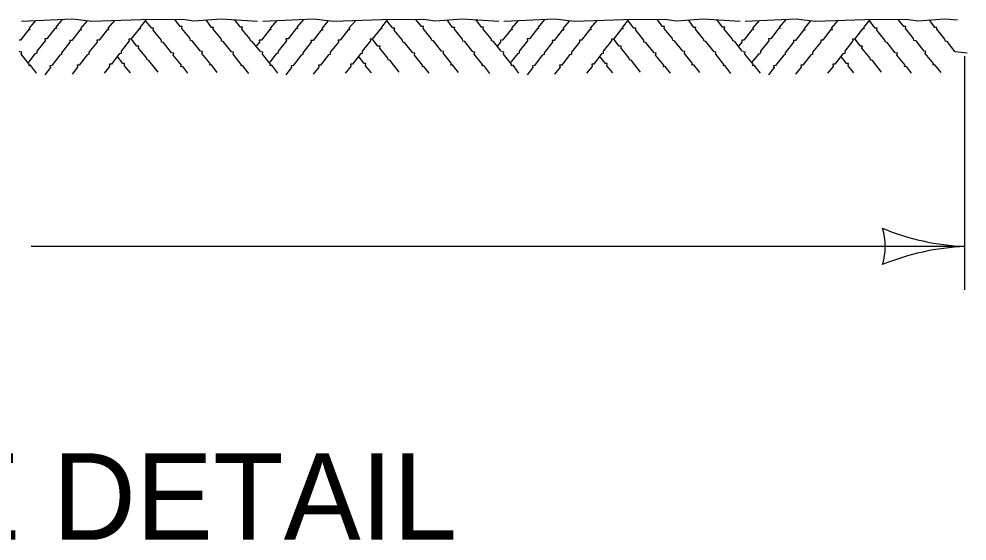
# Model space of a CAD drawing. Extents: x 49991.4 to 50021, y 49987.6 to 50011.4.
# Drawn here: x 50005.452 to 50006.329, y 49996.72 to 49997.202 of the extents above; entities that cross this region are included whole.
import ezdxf

# ---------------------------------------------------------------- set-up
doc = ezdxf.new("R2010")
doc.units = 0
for name, color, linetype in [('Level 1', 7, 'Continuous'), ('Level 2', 7, 'Continuous'), ('Level 3', 7, 'Continuous')]:
    doc.layers.add(name, color=color, linetype=linetype)

msp = doc.modelspace()

# ---------------------------------------------------------------- linework, layer by layer
at = {"layer": 'Level 1'}
for points in [[(50005.4675, 49997.2012), (50005.4615, 49997.1941), (50005.4623, 49997.1926), (50005.4609, 49997.1926), (50005.4535, 49997.183), (50005.4523, 49997.183)], [(50005.4545, 49997.2006), (50005.5017, 49997.2025), (50005.5195, 49997.2004), (50005.5649, 49997.2019), (50005.6037, 49997.2022), (50005.6141, 49997.2007), (50005.6393, 49997.2025), (50005.6584, 49997.2013), (50005.6729, 49997.2006)], [(50005.4921, 49997.202), (50005.4863, 49997.195), (50005.4869, 49997.1936), (50005.4855, 49997.1936), (50005.4779, 49997.184), (50005.4761, 49997.184), (50005.4763, 49997.1824), (50005.4687, 49997.1726), (50005.4687, 49997.171), (50005.467, 49997.1704), (50005.461, 49997.1626)], [(50005.5149, 49997.2004), (50005.5091, 49997.1936), (50005.5099, 49997.1923), (50005.5085, 49997.1923), (50005.5011, 49997.1827), (50005.4993, 49997.1827), (50005.4994, 49997.181), (50005.4917, 49997.1713), (50005.4917, 49997.1696), (50005.4899, 49997.1689), (50005.4827, 49997.1596), (50005.4809, 49997.1593), (50005.4814, 49997.1576), (50005.476, 49997.151)], [(50005.5405, 49997.2012), (50005.5345, 49997.1941), (50005.5353, 49997.1926), (50005.5337, 49997.1926), (50005.5264, 49997.183), (50005.5243, 49997.183), (50005.5247, 49997.1812), (50005.5169, 49997.1718), (50005.5169, 49997.1698), (50005.5153, 49997.1692), (50005.5079, 49997.1598), (50005.5061, 49997.1598), (50005.5065, 49997.1578), (50005.5013, 49997.1515)], [(50005.5699, 49997.202), (50005.5641, 49997.1947), (50005.5648, 49997.1935), (50005.5633, 49997.1935), (50005.5558, 49997.1839), (50005.554, 49997.1839), (50005.5541, 49997.1822), (50005.5467, 49997.1726), (50005.5467, 49997.1707), (50005.545, 49997.1702), (50005.5377, 49997.1608), (50005.5359, 49997.1606), (50005.5361, 49997.1587), (50005.5309, 49997.1524)], [(50005.6085, 49997.1524), (50005.6037, 49997.1587), (50005.6021, 49997.1584), (50005.6025, 49997.1598), (50005.5948, 49997.169), (50005.5954, 49997.171), (50005.5935, 49997.1712), (50005.5859, 49997.1808), (50005.5841, 49997.1812), (50005.584, 49997.183), (50005.5765, 49997.1922), (50005.5767, 49997.1941), (50005.575, 49997.1941), (50005.5697, 49997.2006)], [(50005.6357, 49997.153), (50005.6303, 49997.1602), (50005.6289, 49997.1599), (50005.629, 49997.1612), (50005.6215, 49997.1706), (50005.6219, 49997.1725), (50005.6201, 49997.1726), (50005.6125, 49997.1824), (50005.6109, 49997.1827), (50005.6105, 49997.1845), (50005.6029, 49997.1936), (50005.6033, 49997.1956), (50005.6014, 49997.1956), (50005.5963, 49997.202)], [(50005.6649, 49997.1522), (50005.6591, 49997.1596), (50005.6577, 49997.1592), (50005.6578, 49997.1605), (50005.6503, 49997.1701), (50005.6507, 49997.1718), (50005.6489, 49997.172), (50005.6413, 49997.1816), (50005.6397, 49997.1821), (50005.6395, 49997.1838), (50005.6319, 49997.193), (50005.6321, 49997.1947), (50005.6303, 49997.1947), (50005.6253, 49997.2016)], [(50005.6753, 49997.1726), (50005.6681, 49997.1816), (50005.6663, 49997.1822), (50005.6661, 49997.1839), (50005.6585, 49997.193), (50005.6589, 49997.195), (50005.6571, 49997.195), (50005.6517, 49997.2019)], [(50005.6908, 49997.2012), (50005.6848, 49997.1941), (50005.6854, 49997.1926), (50005.6841, 49997.1926), (50005.6765, 49997.183), (50005.6757, 49997.183)], [(50005.6779, 49997.2006), (50005.725, 49997.2025), (50005.7429, 49997.2004), (50005.7883, 49997.2019), (50005.8269, 49997.2022), (50005.8375, 49997.2007), (50005.8624, 49997.2025), (50005.8817, 49997.2013), (50005.8963, 49997.2006)], [(50005.7154, 49997.202), (50005.7094, 49997.195), (50005.7101, 49997.1936), (50005.7087, 49997.1936), (50005.7013, 49997.184), (50005.6993, 49997.184), (50005.6997, 49997.1824), (50005.692, 49997.1726), (50005.692, 49997.171), (50005.6903, 49997.1704), (50005.6843, 49997.1626)], [(50005.7381, 49997.2004), (50005.7325, 49997.1936), (50005.7333, 49997.1923), (50005.7317, 49997.1923), (50005.7243, 49997.1827), (50005.7223, 49997.1827), (50005.7227, 49997.181), (50005.7149, 49997.1713), (50005.7149, 49997.1696), (50005.7133, 49997.1689), (50005.7059, 49997.1596), (50005.7041, 49997.1593), (50005.7045, 49997.1576), (50005.6993, 49997.151)], [(50005.7639, 49997.2012), (50005.7575, 49997.1941), (50005.7583, 49997.1926), (50005.7569, 49997.1926), (50005.7495, 49997.183), (50005.7477, 49997.183), (50005.7478, 49997.1812), (50005.7401, 49997.1718), (50005.7401, 49997.1698), (50005.7385, 49997.1692), (50005.7311, 49997.1598), (50005.7295, 49997.1598), (50005.7298, 49997.1578), (50005.7244, 49997.1515)], [(50005.7933, 49997.202), (50005.7873, 49997.1947), (50005.788, 49997.1935), (50005.7867, 49997.1935), (50005.7791, 49997.1839), (50005.7773, 49997.1839), (50005.7775, 49997.1822), (50005.7699, 49997.1726), (50005.7699, 49997.1707), (50005.7681, 49997.1702), (50005.7609, 49997.1608), (50005.7591, 49997.1606), (50005.7593, 49997.1587), (50005.7539, 49997.1524)], [(50005.8317, 49997.1524), (50005.827, 49997.1587), (50005.8255, 49997.1584), (50005.8257, 49997.1598), (50005.8181, 49997.169), (50005.8185, 49997.171), (50005.8167, 49997.1712), (50005.8091, 49997.1808), (50005.8075, 49997.1812), (50005.8071, 49997.183), (50005.7995, 49997.1922), (50005.8, 49997.1941), (50005.7981, 49997.1941), (50005.7929, 49997.2006)], [(50005.8589, 49997.153), (50005.8534, 49997.1602), (50005.8519, 49997.1599), (50005.8523, 49997.1612), (50005.8449, 49997.1706), (50005.8451, 49997.1725), (50005.8433, 49997.1726), (50005.8359, 49997.1824), (50005.8341, 49997.1827), (50005.8337, 49997.1845), (50005.8263, 49997.1936), (50005.8264, 49997.1956), (50005.8247, 49997.1956), (50005.8195, 49997.202)], [(50005.8879, 49997.1522), (50005.8823, 49997.1596), (50005.8809, 49997.1592), (50005.8811, 49997.1605), (50005.8735, 49997.1701), (50005.8739, 49997.1718), (50005.8721, 49997.172), (50005.8647, 49997.1816), (50005.8629, 49997.1821), (50005.8625, 49997.1838), (50005.8551, 49997.193), (50005.8555, 49997.1947), (50005.8535, 49997.1947), (50005.8483, 49997.2016)], [(50005.8984, 49997.1726), (50005.8913, 49997.1816), (50005.8895, 49997.1822), (50005.8894, 49997.1839), (50005.8817, 49997.193), (50005.8821, 49997.195), (50005.8803, 49997.195), (50005.875, 49997.2019)], [(50005.914, 49997.2012), (50005.908, 49997.1941), (50005.9087, 49997.1926), (50005.9073, 49997.1926), (50005.8997, 49997.183), (50005.8989, 49997.183)], [(50005.9009, 49997.2006), (50005.9481, 49997.2025), (50005.9659, 49997.2004), (50006.0115, 49997.2019), (50006.0499, 49997.2022), (50006.0605, 49997.2007), (50006.0855, 49997.2025), (50006.1048, 49997.2013), (50006.1195, 49997.2006)], [(50005.9385, 49997.202), (50005.9327, 49997.195), (50005.9333, 49997.1936), (50005.932, 49997.1936), (50005.9245, 49997.184), (50005.9225, 49997.184), (50005.9229, 49997.1824), (50005.9151, 49997.1726), (50005.9151, 49997.171), (50005.9134, 49997.1704), (50005.9074, 49997.1626)], [(50005.9613, 49997.2004), (50005.9555, 49997.1936), (50005.9563, 49997.1923), (50005.9548, 49997.1923), (50005.9475, 49997.1827), (50005.9457, 49997.1827), (50005.9458, 49997.181), (50005.9381, 49997.1713), (50005.9381, 49997.1696), (50005.9365, 49997.1689), (50005.9291, 49997.1596), (50005.9273, 49997.1593), (50005.9277, 49997.1576), (50005.9224, 49997.151)], [(50005.9869, 49997.2012), (50005.9809, 49997.1941), (50005.9817, 49997.1926), (50005.9801, 49997.1926), (50005.9727, 49997.183), (50005.9709, 49997.183), (50005.971, 49997.1812), (50005.9635, 49997.1718), (50005.9635, 49997.1698), (50005.9615, 49997.1692), (50005.9545, 49997.1598), (50005.9525, 49997.1598), (50005.953, 49997.1578), (50005.9477, 49997.1515)], [(50006.0163, 49997.202), (50006.0105, 49997.1947), (50006.0113, 49997.1935), (50006.0099, 49997.1935), (50006.0023, 49997.1839), (50006.0004, 49997.1839), (50006.0005, 49997.1822), (50005.9929, 49997.1726), (50005.9929, 49997.1707), (50005.9914, 49997.1702), (50005.9841, 49997.1608), (50005.9823, 49997.1606), (50005.9825, 49997.1587), (50005.9773, 49997.1524)], [(50006.055, 49997.1524), (50006.0501, 49997.1587), (50006.0485, 49997.1584), (50006.0489, 49997.1598), (50006.0413, 49997.169), (50006.0418, 49997.171), (50006.04, 49997.1712), (50006.0323, 49997.1808), (50006.0305, 49997.1812), (50006.0304, 49997.183), (50006.0229, 49997.1922), (50006.0231, 49997.1941), (50006.0213, 49997.1941), (50006.0161, 49997.2006)], [(50006.0821, 49997.153), (50006.0767, 49997.1602), (50006.0749, 49997.1599), (50006.0754, 49997.1612), (50006.0679, 49997.1706), (50006.0683, 49997.1725), (50006.0664, 49997.1726), (50006.0589, 49997.1824), (50006.0573, 49997.1827), (50006.0569, 49997.1845), (50006.0493, 49997.1936), (50006.0497, 49997.1956), (50006.0478, 49997.1956), (50006.0429, 49997.202)], [(50006.1109, 49997.1522), (50006.1055, 49997.1596), (50006.1041, 49997.1592), (50006.1043, 49997.1605), (50006.0969, 49997.1701), (50006.0971, 49997.1718), (50006.0955, 49997.172), (50006.0879, 49997.1816), (50006.0861, 49997.1821), (50006.0857, 49997.1838), (50006.0783, 49997.193), (50006.0785, 49997.1947), (50006.0767, 49997.1947), (50006.0717, 49997.2016)], [(50006.1215, 49997.1726), (50006.1145, 49997.1816), (50006.1127, 49997.1822), (50006.1125, 49997.1839), (50006.1049, 49997.193), (50006.1053, 49997.195), (50006.1033, 49997.195), (50006.0981, 49997.2019)], [(50006.1371, 49997.2012), (50006.1311, 49997.1941), (50006.1318, 49997.1926), (50006.1303, 49997.1926), (50006.1229, 49997.183), (50006.1221, 49997.183)], [(50006.1241, 49997.2006), (50006.1714, 49997.2025), (50006.1889, 49997.2004), (50006.2349, 49997.2019), (50006.2733, 49997.2022), (50006.2839, 49997.2007), (50006.3088, 49997.2025), (50006.3207, 49997.2018)], [(50006.1618, 49997.202), (50006.1558, 49997.195), (50006.1565, 49997.1936), (50006.1551, 49997.1936), (50006.1479, 49997.184), (50006.1457, 49997.184), (50006.1461, 49997.1824), (50006.1384, 49997.1726), (50006.1384, 49997.171), (50006.1367, 49997.1704), (50006.1305, 49997.1626)], [(50006.1843, 49997.2004), (50006.1789, 49997.1936), (50006.1795, 49997.1923), (50006.1781, 49997.1923), (50006.1707, 49997.1827), (50006.1689, 49997.1827), (50006.169, 49997.181), (50006.1613, 49997.1713), (50006.1613, 49997.1696), (50006.1599, 49997.1689), (50006.1523, 49997.1596), (50006.1505, 49997.1593), (50006.151, 49997.1576), (50006.1457, 49997.151)], [(50006.2099, 49997.2012), (50006.2039, 49997.1941), (50006.2049, 49997.1926), (50006.2033, 49997.1926), (50006.196, 49997.183), (50006.1941, 49997.183), (50006.1943, 49997.1812), (50006.1865, 49997.1718), (50006.1865, 49997.1698), (50006.1849, 49997.1692), (50006.1775, 49997.1598), (50006.1757, 49997.1598), (50006.1761, 49997.1578), (50006.1708, 49997.1515)], [(50006.2397, 49997.202), (50006.2337, 49997.1947), (50006.2344, 49997.1935), (50006.2329, 49997.1935), (50006.2255, 49997.1839), (50006.2235, 49997.1839), (50006.2239, 49997.1822), (50006.2163, 49997.1726), (50006.2163, 49997.1707), (50006.2145, 49997.1702), (50006.2073, 49997.1608), (50006.2053, 49997.1606), (50006.2057, 49997.1587), (50006.2005, 49997.1524)], [(50006.2781, 49997.1524), (50006.2734, 49997.1587), (50006.2717, 49997.1584), (50006.2721, 49997.1598), (50006.2645, 49997.169), (50006.265, 49997.171), (50006.2631, 49997.1712), (50006.2555, 49997.1808), (50006.2539, 49997.1812), (50006.2535, 49997.183), (50006.2459, 49997.1922), (50006.2464, 49997.1941), (50006.2445, 49997.1941), (50006.2395, 49997.2006)], [(50006.3055, 49997.153), (50006.2998, 49997.1602), (50006.2983, 49997.1599), (50006.2985, 49997.1612), (50006.2909, 49997.1706), (50006.2915, 49997.1725), (50006.2897, 49997.1726), (50006.2823, 49997.1824), (50006.2803, 49997.1827), (50006.2801, 49997.1845), (50006.2727, 49997.1936), (50006.2728, 49997.1956), (50006.271, 49997.1956), (50006.2659, 49997.202)], [(50006.3295, 49997.1709), (50006.3185, 49997.172), (50006.3111, 49997.1816), (50006.3093, 49997.1821), (50006.3089, 49997.1838), (50006.3015, 49997.193), (50006.3017, 49997.1947), (50006.2998, 49997.1947), (50006.2949, 49997.2016)], [(50005.581, 49997.1532), (50005.5723, 49997.1642), (50005.5707, 49997.1646), (50005.5705, 49997.1662), (50005.5629, 49997.1755), (50005.5631, 49997.1773), (50005.5613, 49997.1773), (50005.5563, 49997.1839)], [(50005.6755, 49997.183), (50005.6745, 49997.183), (50005.6747, 49997.1812), (50005.6719, 49997.1778)], [(50005.8041, 49997.1532), (50005.7957, 49997.1642), (50005.7939, 49997.1646), (50005.7935, 49997.1662), (50005.7861, 49997.1755), (50005.7863, 49997.1773), (50005.7844, 49997.1773), (50005.7793, 49997.1839)], [(50005.8985, 49997.183), (50005.8977, 49997.183), (50005.8978, 49997.1812), (50005.8949, 49997.1778)], [(50006.0274, 49997.1532), (50006.0189, 49997.1642), (50006.0171, 49997.1646), (50006.0167, 49997.1662), (50006.0093, 49997.1755), (50006.0095, 49997.1773), (50006.0077, 49997.1773), (50006.0027, 49997.1839)], [(50006.1217, 49997.183), (50006.121, 49997.183), (50006.1211, 49997.1812), (50006.1183, 49997.1778)], [(50006.2505, 49997.1532), (50006.2419, 49997.1642), (50006.2403, 49997.1646), (50006.2399, 49997.1662), (50006.2323, 49997.1755), (50006.2327, 49997.1773), (50006.2308, 49997.1773), (50006.2259, 49997.1839)], [(50005.4685, 49997.1524), (50005.4629, 49997.1598), (50005.4615, 49997.1593), (50005.4617, 49997.1606), (50005.4543, 49997.1701), (50005.4549, 49997.1719), (50005.4529, 49997.172), (50005.4523, 49997.1726)], [(50005.6919, 49997.1524), (50005.6863, 49997.1598), (50005.6847, 49997.1593), (50005.6849, 49997.1606), (50005.6775, 49997.1701), (50005.6779, 49997.1719), (50005.6759, 49997.172), (50005.6757, 49997.1726)], [(50005.9149, 49997.1524), (50005.9095, 49997.1598), (50005.908, 49997.1593), (50005.9081, 49997.1606), (50005.9007, 49997.1701), (50005.9009, 49997.1719), (50005.8993, 49997.172), (50005.8989, 49997.1726)], [(50006.1383, 49997.1524), (50006.1325, 49997.1598), (50006.1311, 49997.1593), (50006.1315, 49997.1606), (50006.124, 49997.1701), (50006.1243, 49997.1719), (50006.1225, 49997.172), (50006.1221, 49997.1726)], [(50005.5553, 49997.1527), (50005.5498, 49997.1593), (50005.5499, 49997.1612), (50005.5483, 49997.1612), (50005.5431, 49997.168)], [(50005.7784, 49997.1527), (50005.773, 49997.1593), (50005.7733, 49997.1612), (50005.7715, 49997.1612), (50005.7664, 49997.168)], [(50006.0017, 49997.1527), (50005.9963, 49997.1593), (50005.9965, 49997.1612), (50005.9949, 49997.1612), (50005.9895, 49997.168)], [(50006.2248, 49997.1527), (50006.2194, 49997.1593), (50006.2199, 49997.1612), (50006.2179, 49997.1612), (50006.2127, 49997.168)]]:
    msp.add_lwpolyline(points, dxfattribs=at)
at = {"layer": 'Level 3'}
for p, q in [((50006.3273, 49997.168), (50006.3273, 49996.9522)), ((50006.3273, 49996.9922), (50005.46363, 49996.9922))]:
    msp.add_line(p, q, dxfattribs=at)
for centre, radius, start, end in [((50006.33646, 49997.21433), 0.22232, 247.45601, 267.63952), ((50006.19909, 49996.9922), 0.05477, 342.13882, 17.86118), ((50006.33879, 49996.75949), 0.233, 92.82731, 112.07716)]:
    msp.add_arc(centre, radius, start, end, dxfattribs=at)

# ---------------------------------------------------------------- texts
at = {"layer": 'Level 2'}
msp.add_text('SLOPE DETAIL', height=0.08, dxfattribs=at).set_placement((50005.0967, 49996.72095))

doc.saveas('drawing.dxf')
